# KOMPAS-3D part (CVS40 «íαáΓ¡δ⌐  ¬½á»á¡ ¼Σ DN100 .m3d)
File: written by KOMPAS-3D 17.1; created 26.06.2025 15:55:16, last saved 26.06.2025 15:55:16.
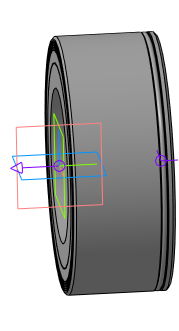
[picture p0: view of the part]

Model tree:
1. Эскиз:1
2. Элемент вращения:1
     Угол 1 = 360
3. Присоединительная точка:1
4. Присоединительная точка:2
